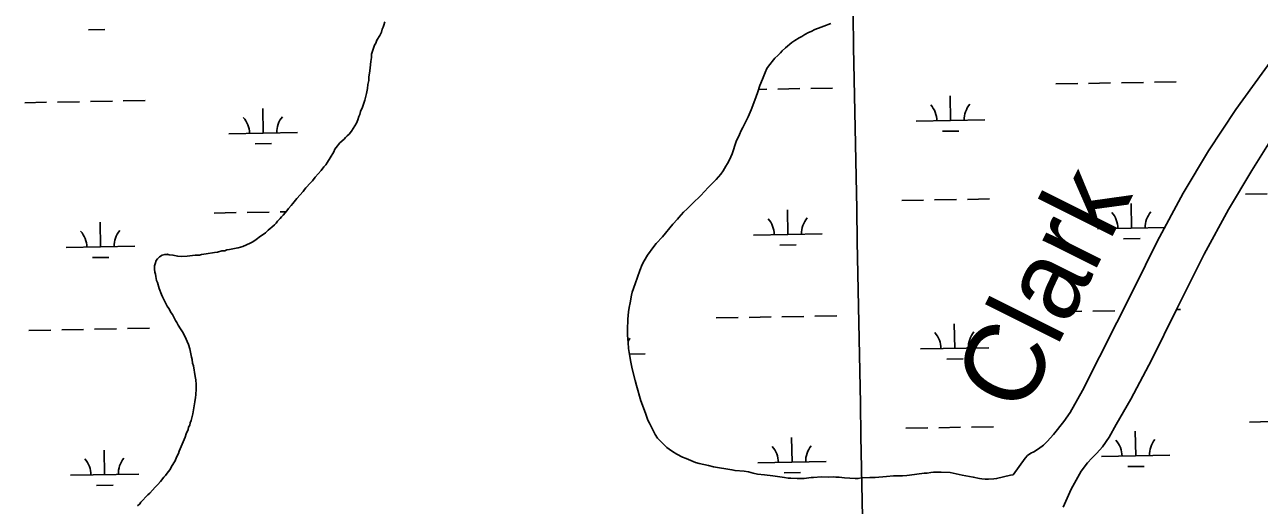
# Model space of a CAD drawing. Extents: x 3957609 to 3995875, y 234277 to 260273.
# Drawn here: x 3971090 to 3972892, y 250496 to 251198 of the extents above; entities that cross this region are included whole.
import ezdxf

# ---------------------------------------------------------------- set-up
doc = ezdxf.new("R2010")
doc.units = 0
for name, color, linetype in [('V-GRID-MAJR', 7, 'Continuous'), ('V-RIVR-IDEN', 7, 'Continuous'), ('V-TOPO-SHOR', 7, 'Continuous'), ('V-WETL-SWMP', 7, 'Continuous')]:
    doc.layers.add(name, color=color, linetype=linetype)

msp = doc.modelspace()

# ---------------------------------------------------------------- linework, layer by layer
at = {"layer": 'V-GRID-MAJR'}
msp.add_spline([(3972513.068, 239900.828), (3972455.83, 242927.648), (3972341.236, 248987.469), (3972226.642, 255047.279), (3972169.287, 258080.274)], degree=3, dxfattribs=at)
at = {"layer": 'V-TOPO-SHOR'}
for points in [[(3971615.623, 251202.061), (3971614.044, 251197.301), (3971613.255, 251194.127), (3971611.674, 251191.348), (3971610.491, 251186.984), (3971608.119, 251182.222), (3971603.769, 251175.474), (3971602.19, 251171.108), (3971600.609, 251167.933), (3971597.449, 251159.205), (3971596.265, 251154.84), (3971595.878, 251150.081), (3971595.094, 251144.131), (3971594.315, 251135.01), (3971593.529, 251130.645), (3971592.355, 251121.126), (3971591.966, 251116.367), (3971590.787, 251110.415), (3971590.4, 251104.865), (3971588.825, 251097.326), (3971587.248, 251091.772), (3971586.461, 251087.805), (3971582.908, 251077.489), (3971580.141, 251071.139), (3971578.96, 251066.774), (3971577.776, 251063.997), (3971576.197, 251058.84), (3971574.223, 251054.079), (3971567.102, 251042.567), (3971563.54, 251038.199), (3971560.372, 251035.417), (3971557.996, 251033.033), (3971556.018, 251030.652), (3971549.681, 251025.089), (3971544.537, 251018.736)], [(3972266.6, 251199.798), (3972256.602, 251195.851), (3972252.496, 251194.416), (3972243.39, 251190.65), (3972238.035, 251188.139), (3972234.287, 251186.347), (3972228.753, 251183.301), (3972224.649, 251180.793), (3972220.543, 251178.82), (3972214.296, 251174.702), (3972210.014, 251171.658), (3972200.736, 251163.96), (3972195.92, 251159.665), (3972193.245, 251156.983), (3972189.141, 251153.044), (3972185.039, 251148.75), (3972175.589, 251137.479), (3972173.451, 251134.082), (3972170.78, 251128.003), (3972167.223, 251118.173), (3972163.129, 251108.875), (3972159.93, 251098.508), (3972156.016, 251087.785), (3972150.323, 251073.662), (3972145.875, 251063.112), (3972138.039, 251047.736), (3972136.079, 251043.445), (3972133.589, 251037.367), (3972128.782, 251027.176), (3972122.736, 251009.481), (3972120.957, 251005.013), (3972119.353, 251001.615), (3972115.97, 250995.178), (3972113.475, 250991.244), (3972109.555, 250984.449), (3972105.992, 250979.439), (3972099.215, 250971.925), (3972087.443, 250960.116), (3972077.099, 250948.488), (3972064.97, 250936.677), (3972056.764, 250928.981), (3972051.771, 250923.971), (3972044.814, 250916.455), (3972042.676, 250913.772), (3972036.077, 250906.438), (3972020.744, 250888.191), (3972011.649, 250878.35), (3972008.259, 250873.877), (3971999.168, 250861.358), (3971994.001, 250853.131), (3971991.33, 250847.589)], [(3972532.783, 250540.647), (3972550.43, 250564.793), (3972553.908, 250568.461), (3972558.815, 250571.953), (3972563.187, 250574.103), (3972570.06, 250578.314), (3972577.108, 250583.862), (3972582.459, 250589.142), (3972591.732, 250599.341), (3972606.888, 250618.569), (3972616.157, 250631.537), (3972634.058, 250663.814), (3972709.39, 250812.216), (3972743.401, 250881.053), (3972781.162, 250951.683), (3972818.043, 251013.645), (3972858.232, 251074.184), (3972910.551, 251146.443)], [(3971544.537, 251018.736), (3971542.558, 251015.957), (3971540.977, 251012.386), (3971535.837, 251003.256), (3971531.88, 250997.302), (3971529.509, 250993.333), (3971526.738, 250990.154), (3971522.781, 250984.994), (3971518.427, 250979.831), (3971514.073, 250975.065), (3971509.719, 250969.904), (3971506.946, 250967.123), (3971500.218, 250959.578), (3971498.238, 250957.194), (3971496.259, 250954.415), (3971487.156, 250944.091), (3971481.219, 250936.941), (3971478.843, 250933.767), (3971474.886, 250929.396), (3971472.511, 250926.22), (3971466.971, 250919.47), (3971464.595, 250917.088), (3971462.617, 250914.704), (3971458.658, 250910.733), (3971456.678, 250907.954), (3971454.304, 250905.57), (3971450.341, 250902.392), (3971447.967, 250900.008), (3971445.194, 250897.624), (3971441.236, 250893.653), (3971438.065, 250891.664), (3971434.104, 250888.883), (3971427.768, 250884.113), (3971422.617, 250880.933), (3971419.052, 250878.944), (3971408.353, 250874.168), (3971401.615, 250872.173), (3971398.443, 250871.377), (3971388.532, 250869.378), (3971384.965, 250868.974), (3971381.792, 250867.78), (3971377.432, 250867.377), (3971371.487, 250865.781), (3971366.727, 250864.981), (3971354.835, 250863.375), (3971348.095, 250862.175), (3971344.922, 250861.376), (3971338.578, 250861.366), (3971327.08, 250859.76), (3971319.15, 250859.351), (3971313.201, 250859.738), (3971306.059, 250861.313), (3971300.905, 250861.702), (3971297.73, 250862.488), (3971294.163, 250862.484), (3971290.595, 250861.288), (3971286.632, 250858.902), (3971283.466, 250856.121), (3971281.883, 250853.344), (3971280.304, 250848.582), (3971279.118, 250845.803), (3971279.126, 250841.046), (3971279.532, 250836.286), (3971280.726, 250833.513), (3971281.127, 250829.946), (3971282.325, 250824.395), (3971283.521, 250821.223), (3971285.913, 250812.505), (3971289.497, 250803.784), (3971291.091, 250800.219), (3971293.077, 250796.653), (3971294.671, 250792.69), (3971297.853, 250786.745), (3971300.239, 250783.182), (3971303.42, 250777.238), (3971305.406, 250774.465), (3971309.785, 250765.749), (3971311.771, 250762.976), (3971313.76, 250759.013), (3971317.338, 250753.862), (3971320.121, 250749.504), (3971323.701, 250742.77), (3971328.874, 250730.882), (3971330.869, 250724.539), (3971332.466, 250717.404), (3971333.267, 250712.249), (3971334.066, 250709.079), (3971334.867, 250703.529), (3971336.063, 250699.564), (3971338.864, 250684.103), (3971339.665, 250679.346), (3971340.073, 250672.606), (3971340.083, 250665.864), (3971339.7, 250657.535), (3971338.913, 250653.17), (3971338.131, 250647.223), (3971336.949, 250641.272), (3971335.383, 250629.77), (3971334.199, 250625.801), (3971333.019, 250619.851), (3971331.438, 250616.28)], [(3972605.784, 250493.461), (3972617.623, 250519.563), (3972632.23, 250546.029), (3972641.679, 250557.924), (3972647.921, 250564.811), (3972655.323, 250571.969), (3972663.527, 250581.183), (3972673.151, 250595.493), (3972683.573, 250614.088), (3972704.952, 250650.748), (3972735.408, 250708.858), (3972770.754, 250780.912), (3972811.712, 250862.712), (3972847.247, 250927.889), (3972881.369, 250984.934), (3972908.365, 251027.766)], [(3971991.33, 250847.589), (3971987.771, 250838.83), (3971981.195, 250819.169), (3971976.925, 250807.37), (3971975.86, 250803.08), (3971973.912, 250791.644), (3971972.495, 250784.853), (3971971.434, 250778.42), (3971970.558, 250767.699), (3971970.564, 250763.59), (3971970.039, 250756.799), (3971970.06, 250744.653), (3971970.605, 250739.115), (3971970.613, 250733.577), (3971971.52, 250725.004), (3971972.243, 250719.286), (3971974.588, 250705.177), (3971976.571, 250695.355), (3971981.064, 250678.033), (3971983.218, 250670.89), (3971989.33, 250648.747), (3971991.662, 250641.962), (3971996.508, 250629.106), (3971999.557, 250620.538), (3972001.888, 250615.717), (3972005.294, 250609.292), (3972008.161, 250603.044), (3972010.131, 250599.474), (3972013.891, 250594.12), (3972016.576, 250590.907), (3972023.378, 250584.13), (3972027.314, 250580.565), (3972030.711, 250577.89), (3972035.362, 250574.681), (3972041.799, 250570.761), (3972050.383, 250566.489), (3972055.566, 250564.353), (3972065.579, 250559.902), (3972069.333, 250558.479), (3972074.338, 250556.88), (3972088.098, 250553.865), (3972095.424, 250552.089), (3972122.23, 250547.846), (3972127.056, 250546.781), (3972140.456, 250545.73), (3972146.71, 250544.669), (3972153.501, 250542.894), (3972159.756, 250541.653), (3972170.121, 250540.598), (3972181.913, 250539.009), (3972199.067, 250536.357), (3972204.607, 250535.65), (3972208.181, 250535.656), (3972217.651, 250535.136), (3972221.759, 250535.142), (3972228.012, 250535.333), (3972237.836, 250536.418), (3972241.408, 250536.424), (3972252.483, 250537.336), (3972263.383, 250536.996), (3972270.17, 250537.364), (3972274.278, 250537.014), (3972279.103, 250536.844), (3972286.787, 250535.961), (3972302.51, 250535.273), (3972306.262, 250534.923), (3972311.619, 250536.002), (3972323.766, 250536.735), (3972331.626, 250536.572), (3972348.059, 250538.206), (3972358.42, 250538.759), (3972371.464, 250538.779), (3972377.536, 250539.324), (3972381.823, 250540.045), (3972403.257, 250542.939), (3972407.365, 250543.123), (3972412.901, 250543.67), (3972416.475, 250544.211), (3972421.118, 250544.575), (3972427.907, 250544.585), (3972440.95, 250543.713), (3972458.643, 250539.812), (3972474.726, 250537.159), (3972483.661, 250535.208), (3972487.235, 250534.677), (3972491.88, 250534.327), (3972497.062, 250534.157), (3972504.744, 250534.528), (3972508.852, 250535.07), (3972528.853, 250539.926), (3972532.783, 250540.647)], [(3971331.438, 250616.28), (3971330.652, 250613.105), (3971328.673, 250609.931), (3971328.282, 250606.757), (3971325.515, 250600.408), (3971323.938, 250595.646), (3971315.247, 250575.011), (3971314.063, 250571.441), (3971311.294, 250566.28), (3971309.32, 250561.121), (3971304.179, 250552.786), (3971302.203, 250548.419), (3971299.432, 250544.848), (3971295.475, 250539.287), (3971293.1, 250536.905), (3971287.955, 250530.553), (3971283.996, 250526.182), (3971280.038, 250522.211), (3971272.517, 250513.474), (3971269.744, 250511.09), (3971259.451, 250500.764), (3971257.87, 250497.985), (3971254.304, 250495.204)]]:
    msp.add_lwpolyline(points, dxfattribs=at)
at = {"layer": 'V-WETL-SWMP'}
for p, q in [((3971182.655, 251190.29), (3971206.651, 251190.726)), ((3972595.204, 251111.317), (3972627.199, 251111.899)), ((3972643.196, 251112.189), (3972675.191, 251112.771)), ((3972691.188, 251113.062), (3972723.183, 251113.644)), ((3972739.18, 251113.935), (3972771.175, 251114.516)), ((3972161.448, 251103.43), (3972173.366, 251103.646)), ((3972189.363, 251103.937), (3972221.358, 251104.519)), ((3972237.355, 251104.81), (3972269.35, 251105.392)), ((3972441.56, 251057.773), (3972440.906, 251093.767)), ((3971089.729, 251083.943), (3971121.724, 251084.524)), ((3971137.721, 251084.815), (3971169.716, 251085.397)), ((3971185.713, 251085.688), (3971217.708, 251086.27)), ((3971233.705, 251086.561), (3971265.7, 251087.142)), ((3971437.91, 251039.523), (3971437.256, 251075.517)), ((3972391.569, 251056.864), (3972491.552, 251058.682)), ((3971387.918, 251038.614), (3971487.902, 251040.432)), ((3972429.843, 251042.126), (3972453.839, 251042.562)), ((3971426.193, 251023.877), (3971450.189, 251024.313)), ((3972872.088, 250950.15), (3972904.083, 250950.732)), ((3972204.071, 250891.566), (3972203.416, 250927.56)), ((3972370.263, 250941.025), (3972402.258, 250941.607)), ((3972418.255, 250941.898), (3972450.25, 250942.48)), ((3972466.247, 250942.77), (3972498.242, 250943.352)), ((3972705.896, 250900.69), (3972705.241, 250936.684)), ((3971366.613, 250922.776), (3971398.608, 250923.357)), ((3971414.605, 250923.648), (3971446.6, 250924.23)), ((3971462.597, 250924.521), (3971471.245, 250924.678)), ((3971200.421, 250873.316), (3971199.766, 250909.31)), ((3972154.079, 250890.657), (3972254.062, 250892.475)), ((3972655.904, 250899.781), (3972754.371, 250901.572)), ((3971150.429, 250872.407), (3971250.412, 250874.225)), ((3972192.353, 250875.919), (3972216.349, 250876.355)), ((3972694.178, 250885.044), (3972718.174, 250885.48)), ((3971188.703, 250857.67), (3971212.699, 250858.106)), ((3972099.427, 250769.572), (3972131.422, 250770.154)), ((3972147.419, 250770.445), (3972179.414, 250771.026)), ((3972195.411, 250771.317), (3972227.406, 250771.899)), ((3972243.403, 250772.19), (3972275.398, 250772.772)), ((3972601.252, 250778.697), (3972633.247, 250779.279)), ((3972649.244, 250779.569), (3972681.239, 250780.151)), ((3972771.192, 250781.787), (3972777.223, 250781.896)), ((3971095.777, 250751.323), (3971127.772, 250751.904)), ((3971143.769, 250752.195), (3971175.764, 250752.777)), ((3971191.761, 250753.068), (3971223.756, 250753.65)), ((3971239.753, 250753.94), (3971271.748, 250754.522)), ((3972447.608, 250725.153), (3972446.954, 250761.147)), ((3971972.704, 250716.517), (3971995.775, 250716.937)), ((3972397.617, 250724.244), (3972497.6, 250726.062)), ((3972435.891, 250709.506), (3972459.887, 250709.942)), ((3972376.311, 250608.405), (3972408.306, 250608.987)), ((3972424.303, 250609.278), (3972456.298, 250609.86)), ((3972472.295, 250610.15), (3972504.29, 250610.732)), ((3972711.944, 250568.07), (3972711.289, 250604.064)), ((3972878.136, 250617.53), (3972910.131, 250618.112)), ((3972210.119, 250558.946), (3972209.464, 250594.94)), ((3971206.469, 250540.696), (3971205.814, 250576.69)), ((3972661.952, 250567.161), (3972761.936, 250568.979)), ((3972160.127, 250558.037), (3972260.11, 250559.855)), ((3972700.226, 250552.424), (3972724.222, 250552.86)), ((3971156.477, 250539.787), (3971256.46, 250541.605)), ((3972198.401, 250543.299), (3972222.397, 250543.735)), ((3971194.751, 250525.05), (3971218.747, 250525.486))]:
    msp.add_line(p, q, dxfattribs=at)
for points in [[(3971615.622, 251202.062), (3971614.043, 251197.301), (3971613.255, 251194.127), (3971611.674, 251191.348), (3971610.491, 251186.984), (3971608.119, 251182.222), (3971603.768, 251175.473), (3971602.189, 251171.108), (3971600.608, 251167.933), (3971597.449, 251159.204), (3971596.266, 251154.84), (3971595.878, 251150.08), (3971595.094, 251144.131), (3971594.316, 251135.009), (3971593.53, 251130.645), (3971592.355, 251121.126), (3971591.966, 251116.366), (3971590.786, 251110.416), (3971590.399, 251104.864), (3971588.825, 251097.326), (3971587.247, 251091.772), (3971586.461, 251087.805), (3971582.908, 251077.489), (3971580.142, 251071.139), (3971578.96, 251066.775), (3971577.775, 251063.997), (3971576.197, 251058.84), (3971574.222, 251054.078), (3971567.102, 251042.566), (3971563.54, 251038.198), (3971560.372, 251035.417), (3971557.996, 251033.034), (3971556.018, 251030.651), (3971549.681, 251025.089), (3971544.536, 251018.736), (3971542.558, 251015.957), (3971540.978, 251012.385), (3971535.837, 251003.256), (3971531.881, 250997.301), (3971529.508, 250993.332), (3971526.737, 250990.155), (3971522.78, 250984.993), (3971518.426, 250979.831), (3971514.072, 250975.065), (3971509.718, 250969.903), (3971506.946, 250967.122), (3971500.217, 250959.577), (3971498.238, 250957.194), (3971496.26, 250954.415), (3971487.155, 250944.09), (3971481.219, 250936.942), (3971478.844, 250933.766), (3971474.886, 250929.397), (3971472.511, 250926.221), (3971466.971, 250919.47)], [(3972056.765, 250928.981), (3972064.97, 250936.677), (3972077.099, 250948.487), (3972087.443, 250960.116), (3972099.214, 250971.926), (3972105.991, 250979.44), (3972109.556, 250984.448), (3972113.475, 250991.243), (3972115.97, 250995.178), (3972119.354, 251001.615), (3972120.957, 251005.012), (3972122.736, 251009.481), (3972128.781, 251027.177), (3972133.589, 251037.368), (3972136.08, 251043.446), (3972138.038, 251047.737), (3972145.874, 251063.113), (3972150.323, 251073.661), (3972156.017, 251087.784), (3972159.93, 251098.509), (3972163.129, 251108.876), (3972167.223, 251118.172), (3972170.781, 251128.004), (3972173.451, 251134.082), (3972175.589, 251137.48), (3972185.039, 251148.75), (3972189.141, 251153.045), (3972193.244, 251156.982), (3972195.919, 251159.666), (3972200.736, 251163.961), (3972210.013, 251171.658), (3972214.296, 251174.702), (3972220.542, 251178.821), (3972224.648, 251180.793), (3972228.753, 251183.301), (3972234.286, 251186.347), (3972238.035, 251188.139), (3972243.391, 251190.649), (3972252.496, 251194.415), (3972256.602, 251195.851), (3972266.6, 251199.798)], [(3972910.55, 251146.444), (3972858.232, 251074.183), (3972818.043, 251013.645), (3972781.162, 250951.682), (3972743.401, 250881.053), (3972709.389, 250812.217), (3972634.058, 250663.813), (3972616.156, 250631.537), (3972606.887, 250618.57), (3972591.732, 250599.34), (3972582.459, 250589.142), (3972577.108, 250583.863), (3972570.06, 250578.314), (3972563.188, 250574.104), (3972558.815, 250571.953), (3972553.908, 250568.462), (3972550.43, 250564.794), (3972532.782, 250540.647), (3972528.853, 250539.926), (3972508.851, 250535.07), (3972504.743, 250534.527), (3972497.062, 250534.158), (3972491.881, 250534.328), (3972487.235, 250534.678), (3972483.661, 250535.208), (3972474.726, 250537.159), (3972458.643, 250539.812), (3972440.95, 250543.714), (3972427.907, 250544.586), (3972421.118, 250544.575), (3972416.474, 250544.211), (3972412.902, 250543.669), (3972407.365, 250543.124), (3972403.256, 250542.939), (3972381.822, 250540.046), (3972377.536, 250539.324), (3972371.463, 250538.779), (3972358.421, 250538.758), (3972348.06, 250538.205), (3972331.627, 250536.571), (3972323.766, 250536.736), (3972311.619, 250536.002), (3972306.261, 250534.922), (3972302.509, 250535.273), (3972286.787, 250535.962), (3972279.103, 250536.843), (3972274.279, 250537.014), (3972270.17, 250537.365), (3972263.382, 250536.996), (3972252.483, 250537.336), (3972241.408, 250536.425), (3972237.835, 250536.419), (3972228.011, 250535.332), (3972221.759, 250535.143), (3972217.65, 250535.136)], [(3972605.784, 250493.462), (3972617.623, 250519.564), (3972632.23, 250546.029), (3972641.679, 250557.924), (3972647.921, 250564.812), (3972655.323, 250571.97), (3972663.527, 250581.184), (3972673.151, 250595.492), (3972683.572, 250614.089), (3972704.951, 250650.747), (3972735.407, 250708.858), (3972770.754, 250780.913), (3972811.712, 250862.712), (3972847.248, 250927.889), (3972881.368, 250984.934), (3972908.365, 251027.765)], [(3972217.65, 250535.136), (3972208.181, 250535.657), (3972204.608, 250535.651), (3972199.068, 250536.357), (3972181.913, 250539.009), (3972170.12, 250540.598), (3972159.756, 250541.653), (3972153.502, 250542.893), (3972146.71, 250544.669), (3972140.456, 250545.731), (3972127.055, 250546.781), (3972122.23, 250547.845), (3972095.425, 250552.09), (3972088.098, 250553.864), (3972074.337, 250556.879), (3972069.332, 250558.479), (3972065.578, 250559.902), (3972055.566, 250564.352), (3972050.382, 250566.488), (3972041.8, 250570.761), (3972035.362, 250574.681), (3972030.712, 250577.89), (3972027.313, 250580.564), (3972023.377, 250584.131), (3972016.577, 250590.908), (3972013.892, 250594.12), (3972010.132, 250599.473), (3972008.161, 250603.043), (3972005.293, 250609.291), (3972001.888, 250615.717), (3971999.558, 250620.537), (3971996.507, 250629.107), (3971991.663, 250641.962), (3971989.329, 250648.747), (3971983.219, 250670.89), (3971981.064, 250678.033), (3971976.57, 250695.355), (3971974.589, 250705.177), (3971972.244, 250719.287), (3971971.52, 250725.003), (3971970.613, 250733.577), (3971970.604, 250739.115), (3971970.059, 250744.652), (3971970.039, 250756.8), (3971970.564, 250763.59), (3971970.558, 250767.699), (3971971.434, 250778.419), (3971972.495, 250784.853), (3971973.913, 250791.644), (3971975.86, 250803.08), (3971976.925, 250807.37), (3971981.194, 250819.168), (3971987.772, 250838.83), (3971991.331, 250847.589), (3971994.002, 250853.132), (3971999.169, 250861.358), (3972008.26, 250873.878), (3972011.648, 250878.35), (3972020.743, 250888.191), (3972036.078, 250906.438), (3972042.676, 250913.773), (3972044.815, 250916.456), (3972051.771, 250923.971), (3972056.765, 250928.981)], [(3971466.971, 250919.47), (3971464.595, 250917.087), (3971462.616, 250914.705), (3971458.657, 250910.733), (3971456.678, 250907.954), (3971454.303, 250905.57), (3971450.342, 250902.392), (3971447.967, 250900.008), (3971445.195, 250897.624), (3971441.236, 250893.653), (3971438.066, 250891.665), (3971434.105, 250888.882), (3971427.768, 250884.113), (3971422.618, 250880.933), (3971419.052, 250878.944), (3971408.352, 250874.168), (3971401.614, 250872.174), (3971398.443, 250871.376), (3971388.532, 250869.377), (3971384.964, 250868.975), (3971381.793, 250867.78), (3971377.432, 250867.377), (3971371.486, 250865.781), (3971366.728, 250864.98), (3971354.834, 250863.375), (3971348.095, 250862.174), (3971344.923, 250861.376), (3971338.578, 250861.366), (3971327.081, 250859.761), (3971319.15, 250859.351), (3971313.201, 250859.738), (3971306.06, 250861.313), (3971300.904, 250861.701), (3971297.731, 250862.489), (3971294.162, 250862.484), (3971290.595, 250861.288), (3971286.633, 250858.902), (3971283.465, 250856.121), (3971281.883, 250853.343), (3971280.304, 250848.582), (3971279.119, 250845.804), (3971279.127, 250841.045), (3971279.531, 250836.287), (3971280.725, 250833.513), (3971281.128, 250829.945), (3971282.326, 250824.395), (3971283.521, 250821.224), (3971285.914, 250812.504), (3971289.498, 250803.785), (3971291.09, 250800.218), (3971293.078, 250796.653), (3971294.671, 250792.69), (3971297.853, 250786.746), (3971300.238, 250783.181), (3971303.42, 250777.238), (3971305.407, 250774.465), (3971309.784, 250765.748), (3971311.771, 250762.975), (3971313.76, 250759.013), (3971317.337, 250753.863), (3971320.12, 250749.505), (3971323.7, 250742.77), (3971328.875, 250730.881), (3971330.868, 250724.539), (3971332.466, 250717.404), (3971333.267, 250712.25), (3971334.065, 250709.079), (3971334.867, 250703.528), (3971336.063, 250699.564), (3971338.864, 250684.103), (3971339.665, 250679.346), (3971340.072, 250672.605), (3971340.083, 250665.863), (3971339.7, 250657.535), (3971338.914, 250653.171), (3971338.131, 250647.222), (3971336.95, 250641.271), (3971335.383, 250629.769), (3971334.199, 250625.801), (3971333.019, 250619.851), (3971331.439, 250616.279), (3971330.651, 250613.105), (3971328.673, 250609.93), (3971328.282, 250606.757), (3971325.516, 250600.407), (3971323.938, 250595.646), (3971315.246, 250575.011), (3971314.063, 250571.44), (3971311.295, 250566.28), (3971309.32, 250561.121), (3971304.179, 250552.785), (3971302.203, 250548.42), (3971299.433, 250544.847), (3971295.476, 250539.288), (3971293.1, 250536.905), (3971287.955, 250530.552), (3971283.997, 250526.183), (3971280.038, 250522.211), (3971272.517, 250513.475), (3971269.745, 250511.091), (3971259.451, 250500.764)], [(3971259.451, 250500.764), (3971257.869, 250497.985), (3971254.305, 250495.204)]]:
    msp.add_lwpolyline(points, dxfattribs=at)
for centre, start, end in [((3972386.318, 251057.243), 0.269879, 41.813537), ((3972496.785, 251059.252), 140.269876, 181.813534), ((3971382.668, 251038.994), 0.269879, 41.813537), ((3971493.135, 251041.002), 140.269876, 181.813534), ((3972148.828, 250891.036), 0.269879, 41.813537), ((3972259.296, 250893.045), 140.269876, 181.813534), ((3972650.653, 250900.161), 0.269879, 41.813537), ((3972761.121, 250902.169), 140.269876, 181.813534), ((3971145.178, 250872.787), 0.269879, 41.813537), ((3971255.646, 250874.795), 140.269876, 181.813534), ((3972392.366, 250724.623), 0.269879, 41.813537), ((3972502.833, 250726.632), 140.269876, 181.813534), ((3972001.008, 250717.507), 140.269876, 149.59328), ((3972656.701, 250567.541), 0.269879, 41.813537), ((3972767.169, 250569.549), 140.269876, 181.813534), ((3972154.876, 250558.416), 0.269879, 41.813537), ((3972265.344, 250560.425), 140.269876, 181.813534), ((3971151.226, 250540.167), 0.269879, 41.813537), ((3971261.694, 250542.175), 140.269876, 181.813534)]:
    msp.add_arc(centre, 35.246, start, end, dxfattribs=at)

# ---------------------------------------------------------------- texts
at = {"layer": 'V-RIVR-IDEN'}
msp.add_text('Clark', height=115.9998, rotation=63.434953, dxfattribs=at).set_placement((3972546.475, 250625.48))

doc.saveas('drawing.dxf')
